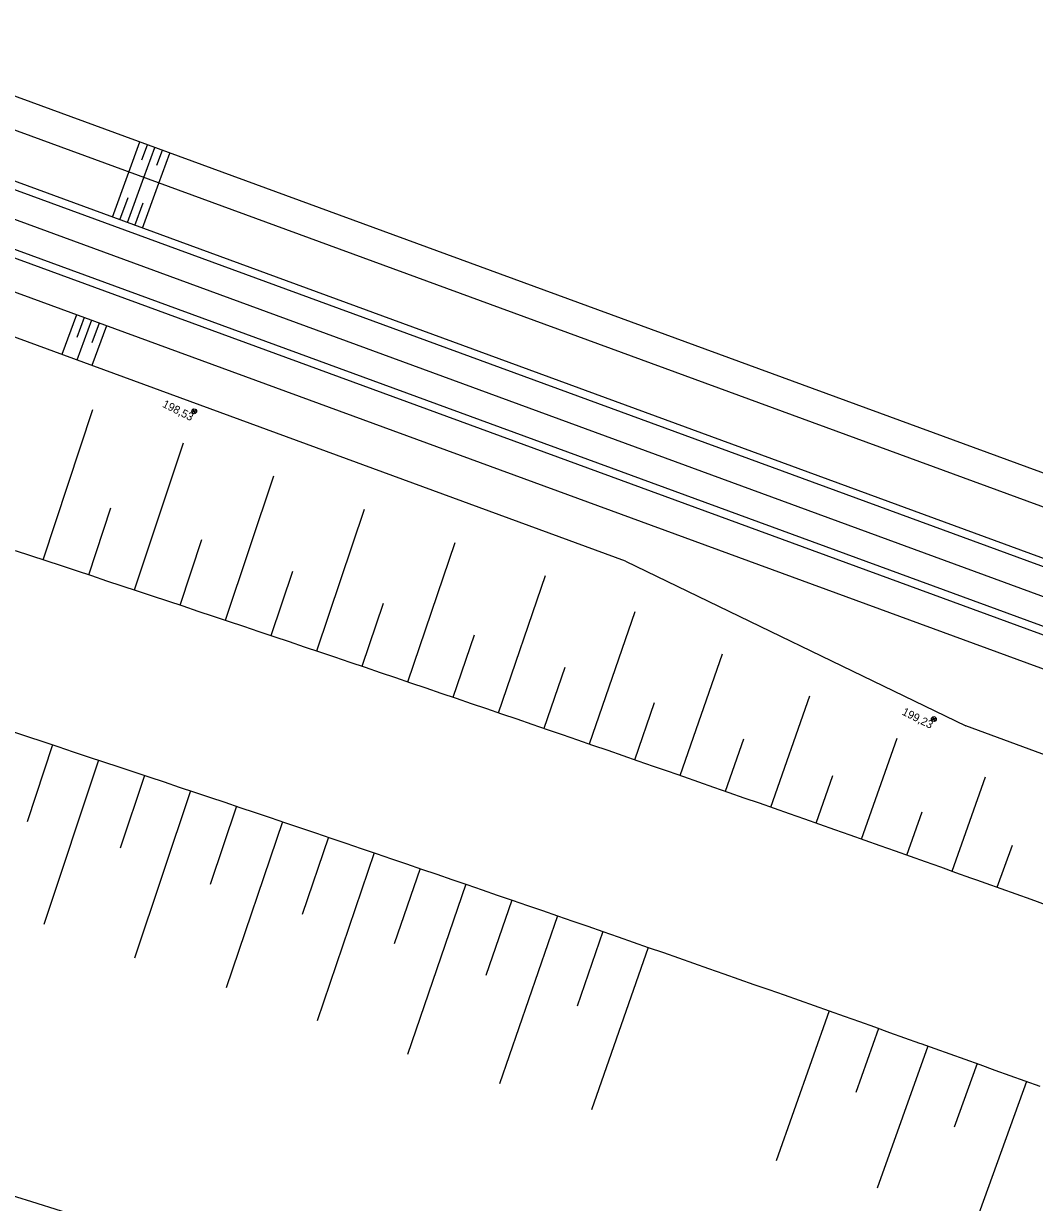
# Model space of a CAD drawing. Extents: x -552278 to -547230, y -1151007 to -1148251.
# Drawn here: x -550833 to -550769.8, y -1148819.7 to -1148746 of the extents above; entities that cross this region are included whole.
import ezdxf

# ---------------------------------------------------------------- set-up
doc = ezdxf.new("R2010")
doc.units = 0
doc.layers.add('SO221815_VYSKOPIS', color=7, linetype='Continuous')
doc.layers.add('u_trat navrh', color=7, linetype='Continuous')

# ---------------------------------------------------------------- blocks, each defined once
blk = doc.blocks.new('SO221824_VYSKOPIS')
at = {"layer": 'SO221815_VYSKOPIS'}
for p, q in [((1.23, -0.85), (-1.23, 0.85)), ((0.86, 1.23), (-0.86, -1.23)), ((0.86, 1.23), (0, 0)), ((0, 0), (1.23, -0.85))]:
    blk.add_line(p, q, dxfattribs=at)
blk.add_lwpolyline([(-0.86, -1.23), (0, 0), (-1.23, 0.85)], dxfattribs=at)
blk.add_circle((0, 0), 1.5, dxfattribs=at)
for start, end in [(145.36204, 235.15382), (325.36204, 55.15382)]:
    blk.add_arc((0, 0), 1.5, start, end, dxfattribs=at)

msp = doc.modelspace()

# ---------------------------------------------------------------- linework, layer by layer
at = {"layer": 'u_trat navrh'}
for p, q in [((-550730.775, -1148788.223), (-550845.881, -1148746.024)), ((-550731.56, -1148790.065), (-550846.569, -1148747.902)), ((-550729.999, -1148793.832), (-550847.602, -1148750.718)), ((-550730.171, -1148794.302), (-550847.774, -1148751.188)), ((-550730.774, -1148795.945), (-550848.376, -1148752.831)), ((-550826.388, -1148755.3), (-550825.699, -1148753.423)), ((-550825.574, -1148754.534), (-550825.23, -1148753.595)), ((-550825.449, -1148755.645), (-550824.761, -1148753.767)), ((-550824.635, -1148754.878), (-550824.291, -1148753.939)), ((-550731.376, -1148797.588), (-550848.979, -1148754.474)), ((-550824.51, -1148755.989), (-550823.822, -1148754.111)), ((-550743.53, -1148793.665), (-550849.151, -1148754.944)), ((-550827.42, -1148758.117), (-550826.388, -1148755.3)), ((-550826.482, -1148758.461), (-550825.449, -1148755.645)), ((-550825.543, -1148758.806), (-550824.51, -1148755.989)), ((-550744.312, -1148795.508), (-550849.839, -1148756.821)), ((-550826.951, -1148758.289), (-550826.435, -1148756.881)), ((-550826.012, -1148758.633), (-550825.496, -1148757.225)), ((-550795.361, -1148779.616), (-550850.751, -1148759.309)), ((-550829.658, -1148764.22), (-550830.57, -1148766.708)), ((-550829.188, -1148764.392), (-550829.644, -1148765.636)), ((-550828.719, -1148764.564), (-550829.631, -1148767.052)), ((-550828.249, -1148764.736), (-550828.706, -1148765.98)), ((-550827.78, -1148764.908), (-550828.692, -1148767.396)), ((-550831.736, -1148779.526), (-550828.646, -1148770.14)), ((-550826.038, -1148781.41), (-550822.986, -1148772.215)), ((-550820.345, -1148783.308), (-550817.328, -1148774.289)), ((-550828.887, -1148780.466), (-550827.505, -1148776.286)), ((-550814.656, -1148785.22), (-550811.669, -1148776.364)), ((-550823.191, -1148782.357), (-550821.826, -1148778.26)), ((-550808.971, -1148787.145), (-550806.012, -1148778.438)), ((-550795.361, -1148779.616), (-550774.106, -1148789.911)), ((-550817.5, -1148784.262), (-550816.149, -1148780.241)), ((-550803.292, -1148789.084), (-550800.355, -1148780.512)), ((-550811.813, -1148786.181), (-550810.475, -1148782.23)), ((-550797.617, -1148791.036), (-550794.757, -1148782.753)), ((-550806.131, -1148788.113), (-550804.805, -1148784.226)), ((-550791.946, -1148793.002), (-550789.3, -1148785.396)), ((-550800.454, -1148790.058), (-550799.137, -1148786.229)), ((-550794.781, -1148792.018), (-550793.542, -1148788.443)), ((-550786.281, -1148794.982), (-550783.846, -1148788.038)), ((-550755.703, -1148796.658), (-550774.106, -1148789.911)), ((-550789.113, -1148793.99), (-550787.97, -1148790.717)), ((-550780.62, -1148796.975), (-550778.395, -1148790.678)), ((-550831.153, -1148791.092), (-550832.745, -1148795.901)), ((-550828.279, -1148792.046), (-550831.696, -1148802.324)), ((-550825.406, -1148793.004), (-550826.924, -1148797.551)), ((-550783.45, -1148795.977), (-550782.401, -1148792.998)), ((-550774.964, -1148798.982), (-550772.867, -1148793.092)), ((-550822.534, -1148793.964), (-550826.036, -1148804.413)), ((-550819.664, -1148794.929), (-550821.312, -1148799.827)), ((-550816.795, -1148795.897), (-550820.3, -1148806.273)), ((-550777.791, -1148797.977), (-550776.837, -1148795.286)), ((-550813.927, -1148796.868), (-550815.559, -1148801.682)), ((-550772.137, -1148799.99), (-550771.195, -1148797.352)), ((-550811.06, -1148797.843), (-550814.631, -1148808.331)), ((-550808.194, -1148798.821), (-550809.805, -1148803.534)), ((-550805.329, -1148799.803), (-550808.982, -1148810.444)), ((-550802.466, -1148800.788), (-550804.094, -1148805.512)), ((-550799.604, -1148801.776), (-550803.232, -1148812.265)), ((-550796.77, -1148802.759), (-550798.39, -1148807.422)), ((-550793.941, -1148803.744), (-550797.478, -1148813.892)), ((-550782.636, -1148807.717), (-550785.951, -1148817.083)), ((-550779.555, -1148808.811), (-550780.979, -1148812.813)), ((-550776.476, -1148809.909), (-550779.645, -1148818.784)), ((-550773.397, -1148811.01), (-550774.821, -1148814.982)), ((-550770.321, -1148812.116), (-550773.482, -1148820.891))]:
    msp.add_line(p, q, dxfattribs=at)
for points in [[(-550833.482, -1148778.952), (-550832.53, -1148779.264), (-550831.579, -1148779.577), (-550830.628, -1148779.891), (-550829.677, -1148780.205), (-550828.727, -1148780.519), (-550827.776, -1148780.834), (-550826.825, -1148781.149), (-550825.875, -1148781.464), (-550824.925, -1148781.78), (-550823.975, -1148782.096), (-550823.025, -1148782.413), (-550822.075, -1148782.73), (-550821.125, -1148783.047), (-550820.175, -1148783.365), (-550819.226, -1148783.683), (-550818.277, -1148784.001), (-550817.327, -1148784.32), (-550816.378, -1148784.639), (-550815.429, -1148784.959), (-550814.48, -1148785.279), (-550813.532, -1148785.599), (-550812.583, -1148785.92), (-550811.635, -1148786.241), (-550810.686, -1148786.563), (-550809.738, -1148786.884), (-550808.79, -1148787.207), (-550807.842, -1148787.529), (-550806.894, -1148787.852), (-550805.946, -1148788.176), (-550804.999, -1148788.499), (-550804.051, -1148788.824), (-550803.104, -1148789.148), (-550802.157, -1148789.473), (-550801.21, -1148789.798), (-550800.263, -1148790.124), (-550799.316, -1148790.45), (-550798.369, -1148790.776), (-550797.423, -1148791.103), (-550796.476, -1148791.43), (-550795.53, -1148791.758), (-550794.584, -1148792.086), (-550793.638, -1148792.414), (-550792.692, -1148792.743), (-550791.746, -1148793.072), (-550790.801, -1148793.401), (-550789.855, -1148793.731), (-550788.91, -1148794.061), (-550787.965, -1148794.392), (-550787.02, -1148794.723), (-550786.075, -1148795.054), (-550785.13, -1148795.386), (-550784.185, -1148795.718), (-550783.241, -1148796.05), (-550782.296, -1148796.383), (-550781.352, -1148796.716), (-550780.408, -1148797.05), (-550779.464, -1148797.384), (-550778.52, -1148797.718), (-550777.576, -1148798.053), (-550776.632, -1148798.388), (-550775.689, -1148798.723), (-550774.746, -1148799.059), (-550773.802, -1148799.395), (-550773.429, -1148799.528), (-550772.859, -1148799.732), (-550771.916, -1148800.069), (-550770.973, -1148800.406), (-550770.031, -1148800.744), (-550769.088, -1148801.082)], [(-550833.661, -1148790.263), (-550832.713, -1148790.576), (-550831.765, -1148790.89), (-550830.817, -1148791.204), (-550829.869, -1148791.518), (-550828.921, -1148791.833), (-550827.973, -1148792.148), (-550827.025, -1148792.463), (-550826.078, -1148792.779), (-550825.131, -1148793.096), (-550824.184, -1148793.412), (-550823.236, -1148793.729), (-550822.289, -1148794.047), (-550821.343, -1148794.364), (-550820.396, -1148794.682), (-550819.449, -1148795.001), (-550818.503, -1148795.32), (-550817.557, -1148795.639), (-550816.61, -1148795.959), (-550815.664, -1148796.279), (-550814.719, -1148796.599), (-550813.773, -1148796.92), (-550812.827, -1148797.241), (-550811.882, -1148797.563), (-550810.936, -1148797.885), (-550809.991, -1148798.207), (-550809.046, -1148798.53), (-550808.101, -1148798.853), (-550807.156, -1148799.176), (-550806.211, -1148799.5), (-550805.266, -1148799.824), (-550804.322, -1148800.149), (-550803.377, -1148800.474), (-550802.433, -1148800.799), (-550801.489, -1148801.125), (-550800.545, -1148801.451), (-550799.601, -1148801.777), (-550798.658, -1148802.104), (-550797.714, -1148802.431), (-550796.77, -1148802.759), (-550795.827, -1148803.087), (-550794.884, -1148803.415), (-550793.941, -1148803.744), (-550792.998, -1148804.073), (-550792.055, -1148804.403), (-550791.112, -1148804.732), (-550790.17, -1148805.063), (-550789.227, -1148805.393), (-550788.285, -1148805.724), (-550787.343, -1148806.056), (-550786.401, -1148806.387), (-550785.459, -1148806.72), (-550784.517, -1148807.052), (-550783.576, -1148807.385), (-550782.634, -1148807.718), (-550781.693, -1148808.052), (-550780.752, -1148808.386), (-550779.811, -1148808.72), (-550778.87, -1148809.055), (-550777.929, -1148809.39), (-550776.988, -1148809.726), (-550776.922, -1148809.749), (-550776.048, -1148810.061), (-550775.107, -1148810.398), (-550774.167, -1148810.734), (-550773.227, -1148811.071), (-550772.287, -1148811.409), (-550771.347, -1148811.746), (-550770.407, -1148812.085), (-550769.468, -1148812.423)]]:
    msp.add_lwpolyline(points, dxfattribs=at)
for radius, start in [(756.5, 67.463408), (754, 51.790749), (753.25, 51.790749), (750, 47.420675)]:
    msp.add_arc((-551056.592, -1149542.18), radius, start, 76.890468, dxfattribs=at)

# ---------------------------------------------------------------- block references
at = {"layer": 'u_trat navrh', "xscale": 0.1, "yscale": 0.09999999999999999, "rotation": -31.851985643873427}
for p in [(-550822.304, -1148770.25), (-550776.099, -1148789.479)]:
    msp.add_blockref('SO221824_VYSKOPIS', p, dxfattribs=at)

# ---------------------------------------------------------------- texts
at = {"layer": 'u_trat navrh'}
for s, p in [('198,53', (-550824.339, -1148769.954)), ('199,23', (-550778.134, -1148789.184))]:
    msp.add_text(s, height=0.5, rotation=333.25678, dxfattribs=at).set_placement(p)

doc.saveas('drawing.dxf')
